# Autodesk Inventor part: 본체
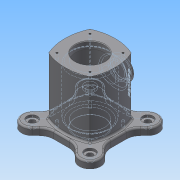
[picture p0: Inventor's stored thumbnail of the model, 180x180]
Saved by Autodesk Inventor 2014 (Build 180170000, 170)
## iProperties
Created: 2016-05
Part Number: 본체
Material: Generic
Document SubType Name: Modeling
Designer: Administrator
Density: 1 g/cm^3
Appearance: Default
Author: Administrator
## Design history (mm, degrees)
sketch "스케치1"
  geometry: L1 (-43, 43)-(43, 43); L2 (43, 43)-(43, -43); L3 (43, -43)-(-43, -43); L4 (-43, -43)-(-43, 43); L5 (-43, 43)-(43, -43); L6 (43, 43)-(-43, -43); L7 (0, 0)-(35.355, 35.355); L8 (0, 0)-(-35.355, -35.355); L9 (0, 0)-(-35.355, 35.355); L10 (0, 0)-(35.355, -35.355); A1 r 85.579 centre (0, -42.579) between (35.355, 35.355) and (-35.355, 35.355); A2 r 86 centre (43, -0.091) between (-35.355, 35.355) and (-35.412, -35.412); A3 r 86 centre (-0.091, 43) between (-35.412, -35.412) and (35.355, -35.355); A4 r 85.579 centre (-42.579, 0) between (35.355, -35.355) and (35.355, 35.355)
  constraints: 20 end point, 9 point on circle, 5 point on line, 4 centre point, 4 tangent, 2 midpoint, 2 parallel, 1 horizontal, 1 perpendicular
  dimensions: "d1" = 86 distance of L2.end L3.end; "d2" = 86 distance of L1.end L2.end; "d3" = 50 distance of L7.start L7.end; "d4" = 50 distance of L7.start L8.end; "d5" = 50 distance of L7.start L9.end; "d6" = 50 distance of L7.start L10.end
extrude "돌출1" new body sketch "스케치1" distance "d7" = 110; taper "d8" = 0 deg
node "작업 평면1"
sketch "스케치2"
  geometry: L1 (35.355, 0)-(-35.355, 0) reference; C1 r 20 at (0, 61); 1 further point
  constraints: 1 centre point, 1 vertical alignment
  dimensions: "d10" = 40 diameter of C1; "d11" = 61 distance from line of L1 C1.centre
extrude "돌출2" join sketch "스케치2" stored distance "d12" = 110; taper "d13" = 10 deg
sketch "스케치4"
  geometry: C1 r 25 at (0, 0); 1 further point
  constraints: 1 centre point, 1 coincident
  dimensions: "d14" = 50 diameter of C1
extrude "돌출3" cut sketch "스케치4" stored distance "d15" = 110; taper "d16" = 0 deg
sketch "스케치5"
  geometry: L1 (0, 12)-(0, 98); L2 (-25, 110)-(25, 110) reference; L3 (55, 41)-(43, 38.884) reference; L4 (43, 38.884)-(43, 0) reference; L5 (43, 0)-(25, 0) reference; L6 (25, 0)-(25, 110) reference; L7 (25, 110)-(43, 110) reference; L8 (43, 110)-(43, 83.116) reference; L9 (43, 83.116)-(55, 81) reference; L10 (55, 81)-(55, 41) reference; L11 (-43, 0)-(-43, 110) reference; L12 (-43, 110)-(-25, 110) reference; L13 (-25, 110)-(-25, 0) reference; L14 (-25, 0)-(-43, 0) reference; L15 (0, 98)-(35, 98); L16 (34, 98)-(34, 12); L17 (34, 12)-(0, 12); 3 further points
  constraints: 8 end point, 2 midpoint, 2 perpendicular, 1 horizontal alignment, 1 parallel, 1 point on line, 1 vertical alignment
  dimensions: "d20" = 86 distance of L1.start L1.end; "d21" = 35 distance of L1.end L15.end; "d22" = 86 distance of L16.start L16.end
revolve "회전1" sketch "스케치5" stored, may be unused: angle "d23" = 90 deg
hole "구멍1" diameter "d26" = 25; stored, may be unused: countersink angle "d30" = 90 deg, drill point angle "d32" = 118 deg; dims "d24" = 10, "d25" = 10, "d27" = 6, "d28" = 30, "d29" = 8, "d31" = 25
sketch "스케치9"
  geometry: L1 (-23.544, 49)-(23.544, 49); L2 (49, 23.544)-(49, -23.544); L3 (23.544, -49)-(-23.544, -49); L4 (-49, -23.544)-(-49, 23.544); L5 (-62.225, 36.77)-(-49, 23.544); L6 (-36.77, 62.225)-(-23.544, 49); L7 (49, -23.544)-(62.225, -36.77); L8 (23.544, -49)-(36.77, -62.225); L9 (36.77, 62.225)-(23.544, 49); L10 (49, 23.544)-(62.225, 36.77); L11 (-49, -23.544)-(-62.225, -36.77); L12 (-36.77, -62.225)-(-23.544, -49); C1 r 25 at (0, 0) reference; C2 r 25 at (0, 0); A1 r 85.579 centre (0, -42.579) between (35.355, 35.355) and (-35.355, 35.355) reference; A2 r 85.579 centre (42.579, 0) between (-35.355, 35.355) and (-35.355, -35.355) reference; A3 r 86 centre (0.091, 43) between (-35.355, -35.355) and (35.412, -35.412) reference; A4 r 86 centre (-43, -0.091) between (35.412, -35.412) and (35.355, 35.355) reference; A5 r 70 centre (0, 0) between (-35.239, 60.483) and (-60.483, -35.239); A6 r 18 centre (49.497, 49.497) between (62.225, 36.77) and (36.77, 62.225); A7 r 18 centre (-49.497, 49.497) between (-36.77, 62.225) and (-62.225, 36.77); A8 r 18 centre (-49.497, -49.497) between (-62.225, -36.77) and (-36.77, -62.225); A9 r 18 centre (49.497, -49.497) between (36.77, -62.225) and (62.225, -36.77)
  constraints: 24 end point, 10 point on circle, 6 centre point, 2 coincident, 2 parallel, 1 horizontal, 1 perpendicular
  dimensions: "d48" = 140 diameter of A5; "d49" = 36 diameter of A6; "d50" = 36 diameter of A7; "d51" = 36 diameter of A8; "d52" = 36 diameter of A9; "d59" = 98 distance between parallel lines of L2 L4; "d60" = 98 distance between parallel lines of L3 L1; "d61" = 36 distance between parallel lines of L6 L5; "d62" = 36 distance between parallel lines of L12 L11; "d63" = 36 distance between parallel lines of L7 L8; "d64" = 36 distance between parallel lines of L9 L10; "d65" = 50 diameter of C2; "d66" = 49 distance from line of L1 C2.centre; "d67" = 49 distance from line of L2 C1.centre; "d68" = 49.49747 horizontal distance of A6.centre C1.centre; "d69" = 90 deg angle of L11 L5; "d70" = 135 deg angle of L7 L2; "d71" = 90 deg angle of L7 L10; "d72" = 90 deg angle of L12 L8; "d73" = 49.49747 horizontal distance of A9.centre C1.centre; "d74" = 49.49747 horizontal distance of A8.centre C2.centre
extrude "돌출5" join sketch "스케치9" distance "d75" = 12; taper "d76" = 0 deg
fillet "모깎기1" dims "d77" = 25
sketch "스케치12"
  geometry: L1 (-49, -13.189)-(-49, 13.189) reference; L2 (-56.322, 30.866)-(-62.225, 36.77) reference; L3 (-36.77, 62.225)-(-30.866, 56.322) reference; L4 (-13.189, 49)-(13.189, 49) reference; L5 (30.866, 56.322)-(36.77, 62.225) reference; L6 (62.225, 36.77)-(56.322, 30.866) reference; L7 (49, 13.189)-(49, -13.189) reference; L8 (56.322, -30.866)-(62.225, -36.77) reference; L9 (36.77, -62.225)-(30.866, -56.322) reference; L10 (13.189, -49)-(-13.189, -49) reference; L11 (-30.866, -56.322)-(-36.77, -62.225) reference; L12 (-62.225, -36.77)-(-56.322, -30.866) reference; C1 r 25 at (0, 0) reference; A1 r 18 centre (49.497, -49.497) between (36.77, -62.225) and (62.225, -36.77) reference; A2 r 18 centre (49.497, 49.497) between (62.225, 36.77) and (36.77, 62.225) reference; A3 r 18 centre (-49.497, 49.497) between (-36.77, 62.225) and (-62.225, 36.77) reference; A4 r 25 centre (-74, -13.189) between (-56.322, -30.866) and (-49, -13.189) reference; A5 r 25 centre (-74, 13.189) between (-49, 13.189) and (-56.322, 30.866) reference; A6 r 18 centre (-49.497, 49.497) between (-36.77, 62.225) and (-62.225, 36.77) reference; A7 r 25 centre (-13.189, 74) between (-30.866, 56.322) and (-13.189, 49) reference; A8 r 25 centre (13.189, 74) between (13.189, 49) and (30.866, 56.322) reference; A9 r 18 centre (49.497, 49.497) between (62.225, 36.77) and (36.77, 62.225) reference; A10 r 25 centre (74, 13.189) between (56.322, 30.866) and (49, 13.189) reference; A11 r 25 centre (74, -13.189) between (49, -13.189) and (56.322, -30.866) reference; A12 r 18 centre (49.497, -49.497) between (36.77, -62.225) and (62.225, -36.77) reference; A13 r 25 centre (13.189, -74) between (30.866, -56.322) and (13.189, -49) reference; A14 r 25 centre (-13.189, -74) between (-13.189, -49) and (-30.866, -56.322) reference; A15 r 18 centre (-49.497, -49.497) between (-62.225, -36.77) and (-36.77, -62.225) reference
hole "구멍2" sketch "스케치12" at (49.497, 49.497), (-49.497, 49.497), (-49.497, -49.497), (49.497, -49.497) diameter "d78" = 10; stored, may be unused: countersink angle "d82" = 90 deg, drill point angle "d84" = 118 deg; dims "d79" = 6, "d80" = 4, "d81" = 2, "d83" = 8
sketch "스케치13"
  geometry: C1 r 5 at (49.497, -49.497) reference; C2 r 5 at (-49.497, 49.497) reference; C3 r 5 at (49.497, 49.497) reference; C4 r 5 at (-49.497, -49.497) reference; C5 r 9 at (-49.497, 49.497); C6 r 9 at (49.497, 49.497); C7 r 9 at (-49.497, -49.497); C8 r 9 at (49.497, -49.497); A1 r 18 centre (49.497, 49.497) between (62.225, 36.77) and (36.77, 62.225) reference; A2 r 18 centre (-49.497, 49.497) between (-36.77, 62.225) and (-62.225, 36.77) reference; A3 r 18 centre (-49.497, -49.497) between (-62.225, -36.77) and (-36.77, -62.225) reference; A4 r 18 centre (49.497, -49.497) between (36.77, -62.225) and (62.225, -36.77) reference; 1 further point
  constraints: 4 centre point, 4 coincident
  dimensions: "d85" = 18 diameter of C5; "d86" = 18 diameter of C6; "d87" = 18 diameter of C7; "d88" = 18 diameter of C8
extrude "돌출6" cut sketch "스케치13" distance "d89" = 4; taper "d90" = 0 deg
sketch "스케치14" dims "d91" = 80
  geometry: L1 (0, 0)-(28.284, 28.284); L2 (0, 0)-(45, 0); C1 r 25 at (0, 0) reference; 1 further point
  constraints: 4 end point, 2 coincident, 1 horizontal, 3 other
  dimensions: "d93" = 45 deg angle of L2 L1
hole "구멍3" sketch "스케치14" at (28.284, 28.284) diameter "d94" = 3.242; stored, may be unused: countersink angle "d98" = 90 deg, drill point angle "d100" = 118 deg; dims "d95" = 7, "d96" = 4, "d97" = 2, "d99" = 10
fillet "모깎기2" dims "d104" = 3
sketch "스케치15" dims "d105" = 80
  geometry: L1 (-62.225, 36.77)-(-56.322, 30.866) reference; L2 (0, 0)-(28.284, 28.284); L3 (0, 0)-(45, 0); C1 r 25 at (0, 0) reference; 1 further point
  constraints: 4 end point, 2 coincident, 1 horizontal, 1 perpendicular, 3 other
  dimensions: "d107" = 45 deg angle of L3 L2 (derived)
hole "구멍4" sketch "스케치15" at (28.284, 28.284) diameter "d108" = 3.242; stored, may be unused: countersink angle "d112" = 90 deg, drill point angle "d114" = 118 deg; dims "d109" = 7, "d110" = 4, "d111" = 2, "d113" = 10
fillet "모깎기3" dims "d118" = 3
fillet "모깎기4" dims "d119" = 3
fillet "모깎기5" dims "d120" = 3
fillet "모깎기6" dims "d121" = 3
chamfer "모따기1" distance "d122" = 1; stored, may be unused: second distance "d123" = 2, angle "d124" = 45 deg
chamfer "모따기2" distance "d125" = 1; stored, may be unused: second distance "d126" = 2, angle "d127" = 45 deg
chamfer "모따기3" distance "d128" = 1; stored, may be unused: second distance "d129" = 2, angle "d130" = 45 deg
node "작업 평면2"
sketch "스케치16"
  geometry: L1 (-35.833, 110)-(-43, 110) reference; L2 (-64.497, 12)-(-58.497, 12) reference; L3 (-58.497, 12)-(-58.497, 8) reference; L4 (-58.497, 8)-(-54.497, 8) reference; L5 (-54.497, 8)-(-54.497, 0) reference; L6 (-54.497, 0)-(-67.497, 0) reference; L7 (-67.497, 0)-(-67.497, 9) reference; L8 (-40.497, 12)-(-26.744, 12) reference; L9 (-18.164, 9)-(-18.164, 0) reference; L10 (-18.164, 0)-(-44.497, 0) reference; L11 (-44.497, 0)-(-44.497, 8) reference; L12 (-44.497, 8)-(-40.497, 8) reference; L13 (-40.497, 8)-(-40.497, 12) reference; L14 (26.744, 12)-(40.497, 12) reference; L15 (40.497, 12)-(40.497, 8) reference; L16 (40.497, 8)-(44.497, 8) reference; L17 (44.497, 8)-(44.497, 0) reference; L18 (44.497, 0)-(18.164, 0) reference; L19 (18.164, 0)-(18.164, 9) reference; L20 (58.497, 12)-(64.497, 12) reference; L21 (67.497, 9)-(67.497, 0) reference; L22 (67.497, 0)-(54.497, 0) reference; L23 (54.497, 0)-(54.497, 8) reference; L24 (54.497, 8)-(58.497, 8) reference; L25 (58.497, 8)-(58.497, 12) reference; C1 r 15 at (0, 61) reference; C2 r 20.97 at (0, 61) reference; 3 further points
  constraints: 5 other
  dimensions: "d132" = 49 distance from line of L1 point (-29, 61); "d133" = 29 distance of point (-29, 61) C1.centre
feature "엠보싱1" sketch "스케치16" dims "d1" = 86, "d2" = 86, "d3" = 50, "d4" = 50, "d5" = 50, "d6" = 50, "d134" = 0.5, "d135" = 0
node "솔리드1"
pattern_circular "원형 패턴1" dims angle "d102" = 360 deg
pattern_circular "원형 패턴2" dims angle "d116" = 360 deg
node "절단 모서리 투영1"
node "절단 모서리 투영2"
node "절단 모서리 투영3"
other parameters: "d9" = 55, "d55" = 18, "d56" = 18, "d57" = 18, "d58" = 18, "d131" = 49.5
